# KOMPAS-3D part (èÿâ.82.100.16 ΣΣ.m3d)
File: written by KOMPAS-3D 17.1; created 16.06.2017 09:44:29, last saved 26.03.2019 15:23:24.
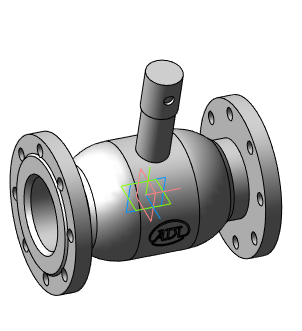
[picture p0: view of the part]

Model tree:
1. Операция без истории:2  (labels: Сталь 20  ГОСТ 1050-88)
